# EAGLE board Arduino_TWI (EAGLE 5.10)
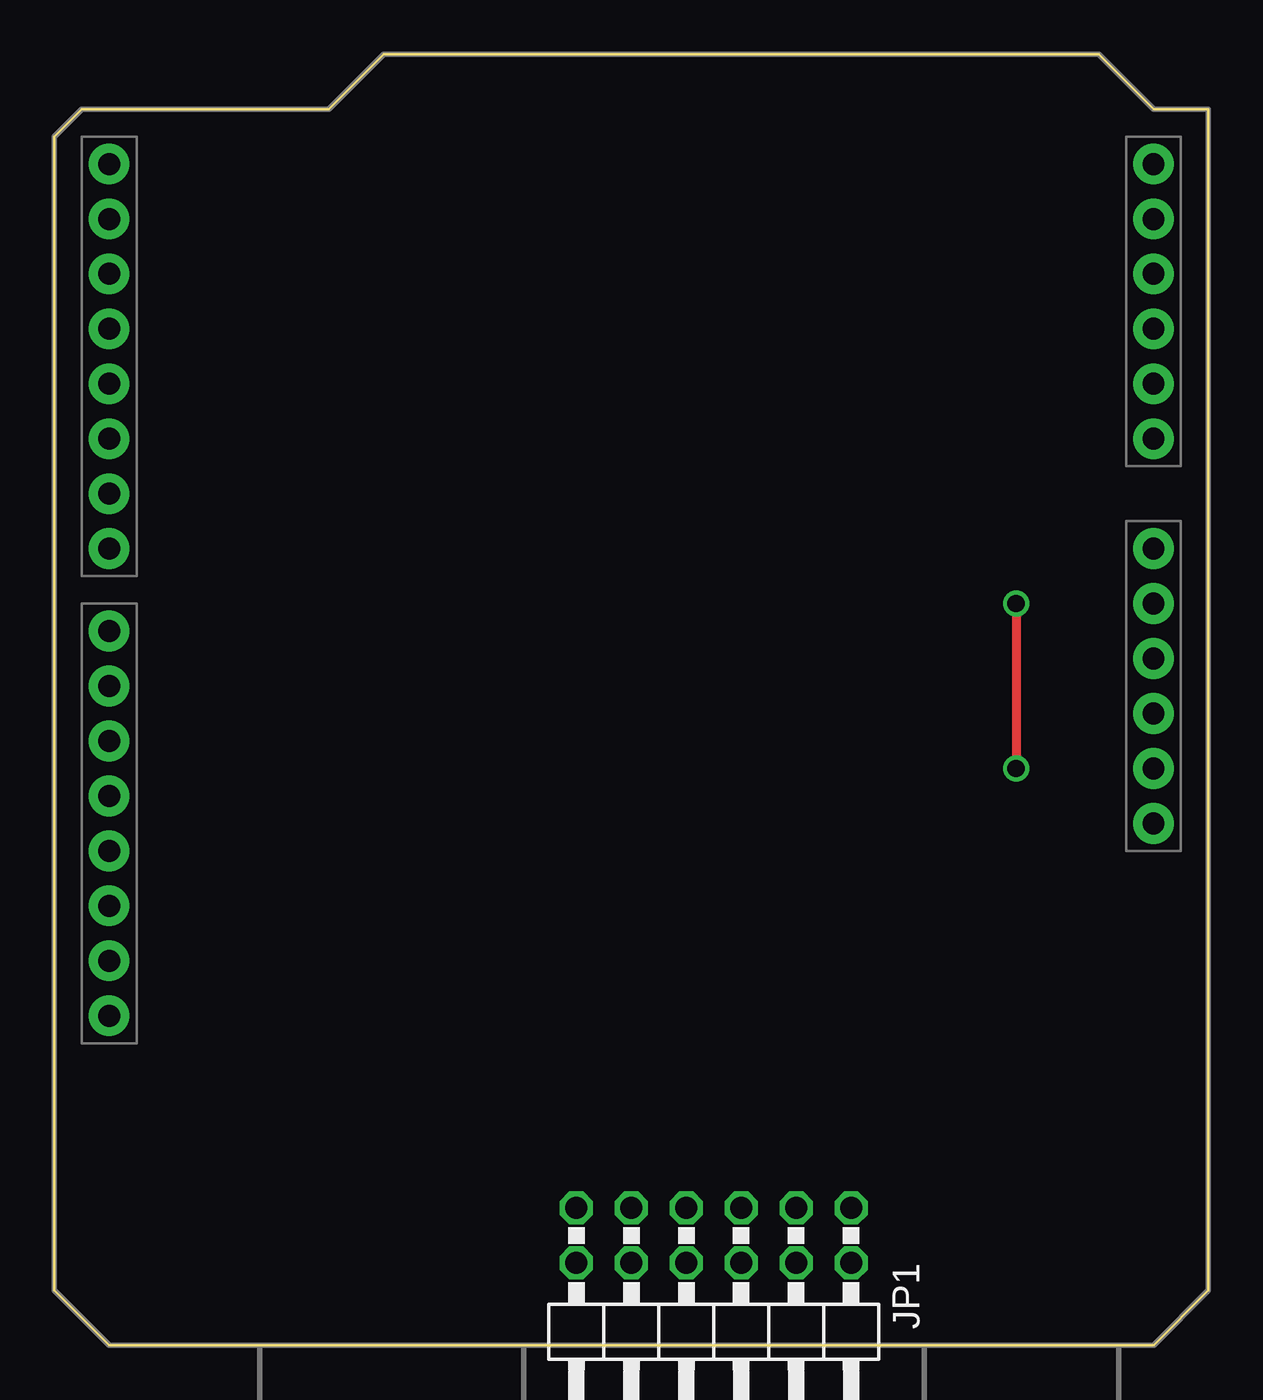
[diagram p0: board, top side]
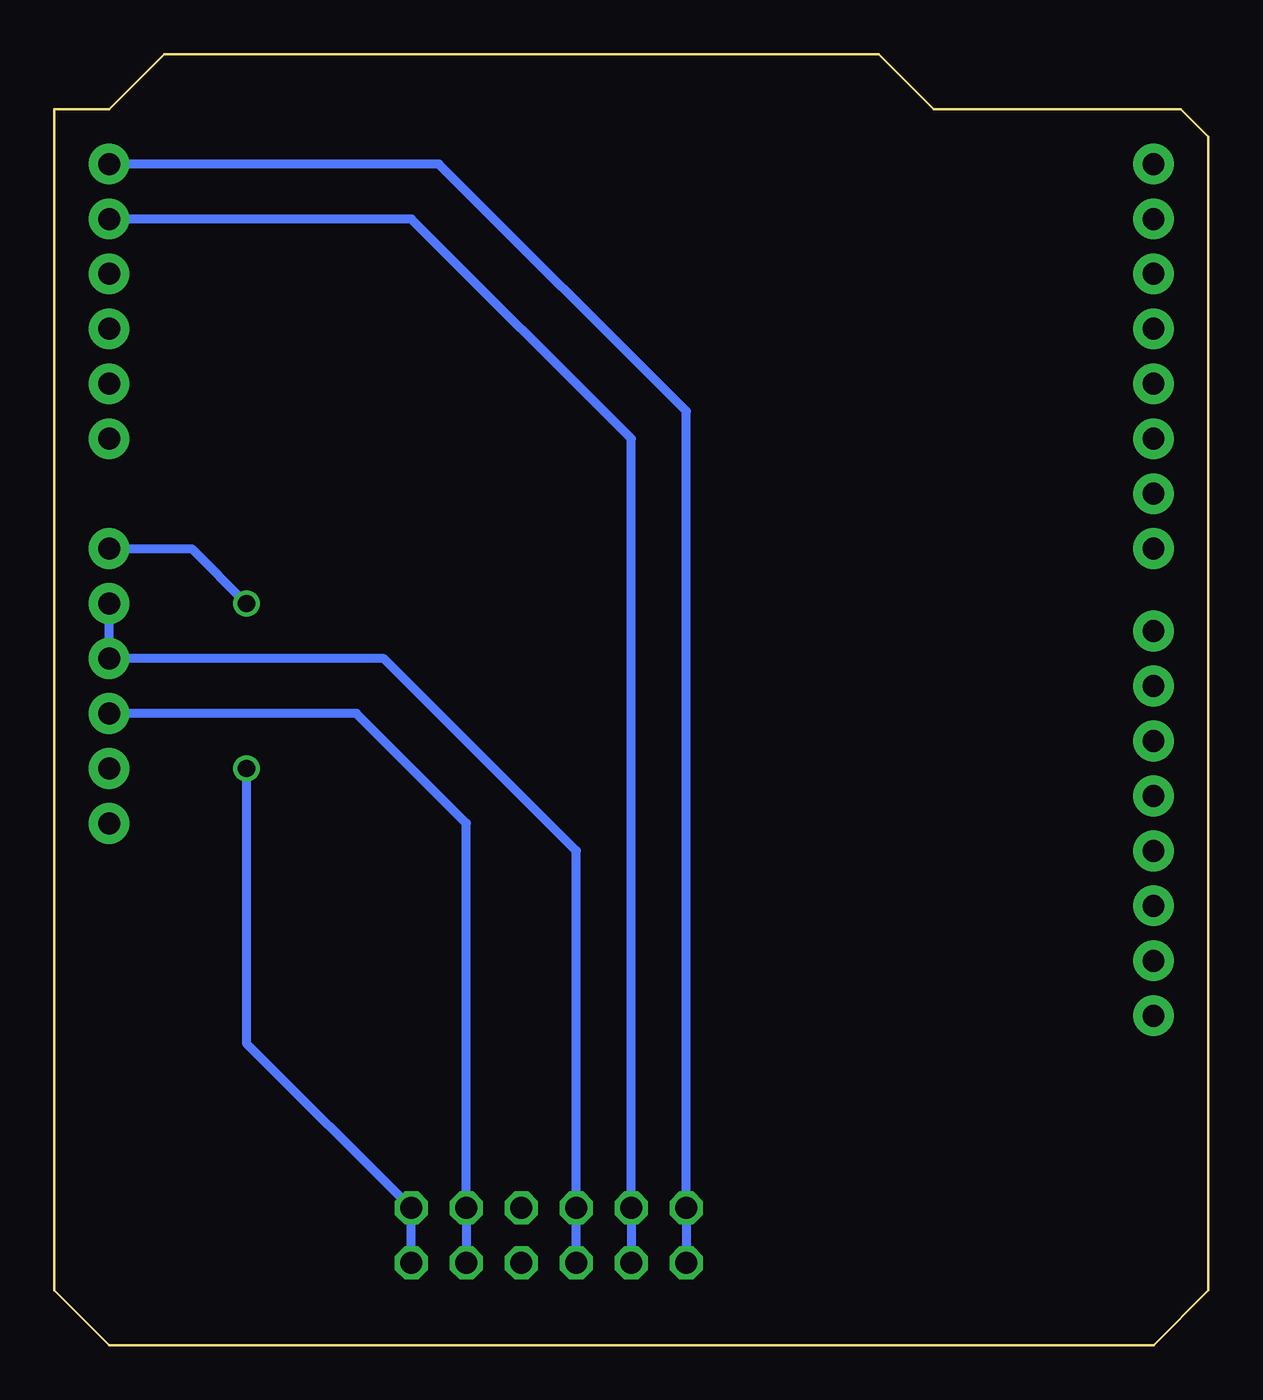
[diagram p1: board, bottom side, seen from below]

Size 53.34 x 59.69 mm. Coordinates in mm from the lower left corner, seen from the top.
Outline: 0,2.54 2.54,0 50.8,0 53.34,2.54 53.34,57.15 50.8,57.15 48.26,59.69 15.24,59.69 12.7,57.15 1.27,57.15 0,55.88 0,2.54
Copper layers (1*16): Top 0.035mm / dielectric 1.5mm / Bottom 0.035mm
Design rules "default": minimum track width 10mil, minimum drill 24mil, track to track 8mil, track to pad 8mil, pad to pad 8mil, via to via 8mil, smd to smd 8mil, copper to edge 40mil, drill to drill 8mil, minimum pad ring 10mil, minimum via ring 8mil, stop-mask expansion 4mil, vias tented up to drill 0mil, thermal gap 10mil

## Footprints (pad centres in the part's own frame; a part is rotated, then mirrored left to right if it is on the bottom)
2X06/90 = drill 1.016 octagon: 1 -6.35,-6.35; 2 -6.35,-3.81; 3 -3.81,-6.35; 4 -3.81,-3.81; 5 -1.27,-6.35; 6 -1.27,-3.81; 7 1.27,-6.35; 8 1.27,-3.81; 9 3.81,-6.35; 10 3.81,-3.81; 11 6.35,-6.35; 12 6.35,-3.81
DUEMILANOVE_SHIELD_NOHOLES_NOLABELS = drill 1.016 pad 1.88 round: 3.3V 50.8,26.67; 5V 50.8,29.21; A0 50.8,41.91; A1 50.8,44.45; A2 50.8,46.99; A3 50.8,49.53; A4 50.8,52.07; A5 50.8,54.61; AREF 2.54,15.24; D2 2.54,49.53; D3 2.54,46.99; D4 2.54,44.45; D5 2.54,41.91; D6 2.54,39.37; D7 2.54,36.83; D8 2.54,33.02; D9 2.54,30.48; D10 2.54,27.94; D11 2.54,25.4; D12 2.54,22.86; D13 2.54,20.32; GND@0 50.8,31.75; GND@1 50.8,34.29; GND@2 2.54,17.78; RES 50.8,24.13; RX 2.54,54.61; TX 2.54,52.07; VIN 50.8,36.83

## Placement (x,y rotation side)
JP1  [2X06/90]  30.48,0 180 top
U1  ARDUINO_SHIELDNOHOLESORLABELS  [DUEMILANOVE_SHIELD_NOHOLES_NOLABELS]  0,0 0 top

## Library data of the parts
JP1 = pinhead
U1 = SparkFun

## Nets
#RESET: U1.RES
+5V: JP1.3 JP1.4 U1.5V
+15V: JP1.1 JP1.2 U1.VIN
GND: JP1.7 JP1.8 U1.GND@0 U1.GND@1
SCL: JP1.11 JP1.12 U1.A5
SDA: JP1.9 JP1.10 U1.A4

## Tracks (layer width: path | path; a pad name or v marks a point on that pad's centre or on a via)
+5V
  Bottom 0.406: U1.5V 39.37,29.21 34.29,24.13 JP1.3 JP1.4
+15V  (via drill 0.8)
  Top 0.406: v44.45,34.29 v44.45,26.67
  Bottom 0.406: JP1.2 JP1.1 44.45,13.97 v44.45,26.67 | U1.VIN 46.99,36.83 v44.45,34.29
GND
  Bottom 0.406: JP1.8 JP1.7 29.21,22.86 38.1,31.75 U1.GND@0 U1.GND@1
SCL
  Bottom 0.406: U1.A5 35.56,54.61 24.13,43.18 JP1.11 JP1.12
SDA
  Bottom 0.406: U1.A4 36.83,52.07 26.67,41.91 JP1.9 JP1.10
